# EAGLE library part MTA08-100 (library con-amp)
AMP connector
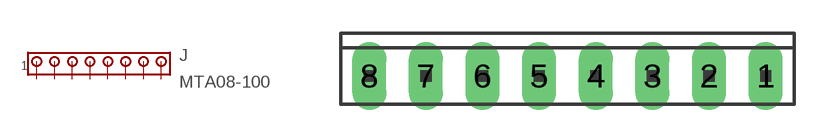
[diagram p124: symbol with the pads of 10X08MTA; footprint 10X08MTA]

Designator prefix J

## MTA08-100 (OC_FARNELL: unknown; OC_NEWARK: unknown)  [10X08MTA]
1  1  pas
2  2  pas
3  3  pas
4  4  pas
5  5  pas
6  6  pas
7  7  pas
8  8  pas

## Footprint 10X08MTA (pad centres in mm)
AMP MTA connector Source: http://ecommas.tycoelectronics.com .. ENG_CD_640456_W.pdf
drill 1.016 long: 1 8.89,0; 2 6.35,0; 3 3.81,0; 4 1.27,0; 5 -1.27,0; 6 -3.81,0; 7 -6.35,0; 8 -8.89,0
